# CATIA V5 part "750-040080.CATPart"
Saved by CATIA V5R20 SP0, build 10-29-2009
Part number: 750-040080
Source: Unknown
Property "ARTICLENO": "750-040080"
Property "BOMINFO": "750-040080"
Property "CODE": "750-040080"
Property "LINA": "750-040080"
Property "NB": "750-040080"
Property "NBSYN": "$CODE."
Property "NN": "750"
Property "NT": "Slide Stop Block"
Property "SUPPLIER": "CF"
Bounding box of the stored display mesh (mm): x 0 to 43, y 0 to 60, z -40 to 40
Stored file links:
  C:\Users\Utente\Desktop\3D files 750\750-040080.CATPart
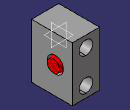
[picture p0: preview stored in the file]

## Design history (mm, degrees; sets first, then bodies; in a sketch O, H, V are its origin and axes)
Body1 "Geometry.1" (main body)
  Solid1 "750-040080.catpart": solid without history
